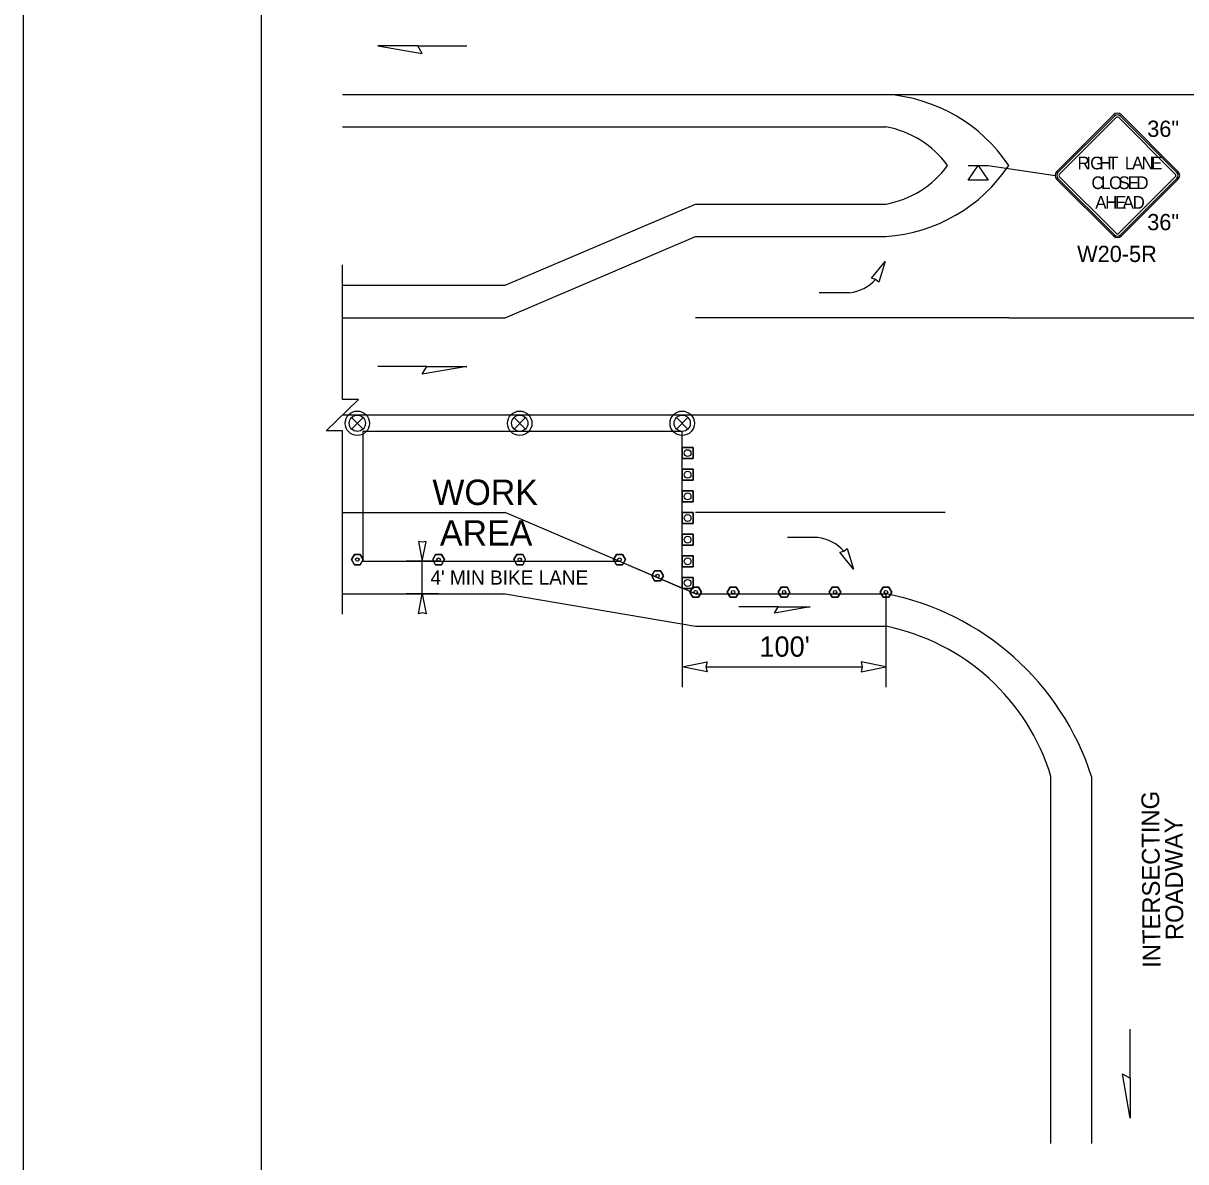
# Model space of a CAD drawing. Extents: x 99958 to 100136, y 99935 to 100013.
# Drawn here: x 100059.062 to 100063.643, y 99971.834 to 99976.321 of the extents above; entities that cross this region are included whole.
import ezdxf

# ---------------------------------------------------------------- set-up
doc = ezdxf.new("R2010")
doc.units = 0
for name, color, linetype in [('RD_ED_ShoulderPavedEdge', 7, 'Continuous'), ('RD_MK_LineEdgeWhite', 7, 'Continuous'), ('RD_MK_LineEdgeYellow', 7, 'Continuous'), ('RD_MK_LineLane', 7, 'Continuous'), ('SH_DE_DetailBody1Text', 7, 'Continuous'), ('SH_GI_PlotLimits', 7, 'Continuous'), ('SH_GI_SheetBorder', 7, 'Continuous'), ('TR_SN_ConstructionSigns', 7, 'Continuous'), ('TR_WZ_ArrowLeftStrRightTurn', 7, 'Continuous'), ('TR_WZ_PortableSignMountBlk-Org', 7, 'Continuous'), ('TR_WZ_TrafficCone', 7, 'Continuous'), ('TR_WZ_TrafficSafetyDrum', 7, 'Continuous'), ('TR_WZ_TubularMarker', 7, 'Continuous'), ('TR_WZ_WorkAreaLabel', 7, 'Continuous'), ('TR_WZ_WorkZoneDetails', 7, 'Continuous'), ('TR_WZ_WorkZoneTextCurrent', 7, 'Continuous')]:
    doc.layers.add(name, color=color, linetype=linetype)

msp = doc.modelspace()

# ---------------------------------------------------------------- linework, layer by layer
at = {"layer": 'RD_ED_ShoulderPavedEdge'}
for p, q in [((100060.32, 99975.9124), (100062.4619, 99975.9124)), ((100060.9619, 99975.2885), (100061.7119, 99975.6084)), ((100061.7119, 99975.6084), (100062.4619, 99975.6084)), ((100060.32, 99975.2885), (100060.9619, 99975.2885)), ((100060.32, 99974.0724), (100060.9619, 99974.0724)), ((100060.9619, 99974.0724), (100061.7119, 99973.9444)), ((100061.7119, 99973.9444), (100062.4619, 99973.9444))]:
    msp.add_line(p, q, dxfattribs=at)
msp.add_lwpolyline([(100063.1119, 99971.9059), (100063.1119, 99973.3524)], dxfattribs=at)
for centre, radius, start, end in [((100062.3952, 99975.5361), 0.3822, 35.9393, 79.9433), ((100062.3952, 99975.9848), 0.3822, 280.0567, 324.0607), ((100062.2915, 99973.1044), 0.8571, 16.8187, 78.5287)]:
    msp.add_arc(centre, radius, start, end, dxfattribs=at)
at = {"layer": 'RD_MK_LineEdgeWhite'}
msp.add_line((100063.2719, 99973.3524), (100063.2719, 99971.9059), dxfattribs=at)
msp.add_arc((100062.257, 99973.0262), 1.0661, 17.8172, 78.9158, dxfattribs=at)
at = {"layer": 'RD_MK_LineEdgeYellow'}
for p, q in [((100060.32, 99976.0404), (100062.4619, 99976.0404)), ((100062.4619, 99976.0404), (100064.3984, 99976.0404)), ((100060.9619, 99975.1604), (100061.7119, 99975.4804)), ((100061.7119, 99975.4804), (100062.4619, 99975.4804)), ((100060.32, 99975.1604), (100060.9619, 99975.1604)), ((100062.9455, 99975.1604), (100064.8819, 99975.1604)), ((100060.32, 99974.3924), (100060.9619, 99974.3924)), ((100061.7119, 99974.0724), (100062.4619, 99974.0724))]:
    msp.add_line(p, q, dxfattribs=at)
for centre, start, end in [((100062.4204, 99975.4112), 33.6284, 86.2234), ((100062.4204, 99976.1097), 273.7766, 326.3716)]:
    msp.add_arc(centre, 0.6306, start, end, dxfattribs=at)
at = {"layer": 'RD_MK_LineLane'}
for points in [[(100062.9455, 99975.1604), (100061.7119, 99975.1604)], [(100067.555, 99974.7764), (100060.32, 99974.7764)], [(100061.7119, 99974.0724), (100060.9619, 99974.3924)], [(100062.6955, 99974.3924), (100061.7119, 99974.3924)]]:
    msp.add_lwpolyline(points, dxfattribs=at)
at = {"layer": 'SH_GI_PlotLimits'}
msp.add_lwpolyline([(100059.0625, 99969.6875), (100076.0625, 99969.6875), (100076.0625, 99980.6875), (100059.0625, 99980.6875)], close=True, dxfattribs=at)
at = {"layer": 'SH_GI_SheetBorder'}
msp.add_line((100060, 99980.375), (100060, 99970), dxfattribs=at)
at = {"layer": 'TR_SN_ConstructionSigns'}
for p, q in [((100063.358, 99975.9599), (100063.1352, 99975.7371)), ((100063.3624, 99975.9554), (100063.1396, 99975.7327)), ((100063.1458, 99975.7265), (100063.3686, 99975.9493)), ((100063.3792, 99975.9493), (100063.6019, 99975.7265)), ((100063.6081, 99975.7327), (100063.3854, 99975.9554)), ((100063.6125, 99975.7371), (100063.3898, 99975.9599)), ((100063.1352, 99975.7053), (100063.358, 99975.4826)), ((100063.1396, 99975.7097), (100063.3624, 99975.487)), ((100063.3686, 99975.4932), (100063.1458, 99975.7159)), ((100063.6019, 99975.7159), (100063.3792, 99975.4932)), ((100063.3854, 99975.487), (100063.6081, 99975.7097)), ((100063.3898, 99975.4826), (100063.6125, 99975.7053))]:
    msp.add_line(p, q, dxfattribs=at)
for centre, radius, start, end in [((100063.3739, 99975.9439), 0.0225, 45, 135), ((100063.3739, 99975.9439), 0.0162, 45, 135), ((100063.3739, 99975.9439), 0.0075, 45, 135), ((100063.1511, 99975.7212), 0.0225, 135, 225), ((100063.1511, 99975.7212), 0.0162, 135, 225), ((100063.1511, 99975.7212), 0.0075, 135, 225), ((100063.5966, 99975.7212), 0.0075, 315, 45), ((100063.5966, 99975.7212), 0.0162, 315, 45), ((100063.5966, 99975.7212), 0.0225, 315, 45), ((100063.3739, 99975.4985), 0.0162, 225, 315), ((100063.3739, 99975.4985), 0.0075, 225, 315), ((100063.3739, 99975.4985), 0.0225, 225, 315)]:
    msp.add_arc(centre, radius, start, end, dxfattribs=at)
at = {"layer": 'TR_WZ_ArrowLeftStrRightTurn'}
for p, q in [((100062.3186, 99975.2587), (100062.1986, 99975.2587)), ((100062.1938, 99974.2942), (100062.0738, 99974.2942))]:
    msp.add_line(p, q, dxfattribs=at)
for points in [[(100062.4588, 99975.3822), (100062.4338, 99975.3003), (100062.4211, 99975.3115), (100062.4047, 99975.3158)], [(100062.3336, 99974.1692), (100062.2798, 99974.2359), (100062.2962, 99974.2402), (100062.309, 99974.2513)]]:
    msp.add_lwpolyline(points, close=True, dxfattribs=at)
for centre, radius, start, end in [((100062.2994, 99975.4218), 0.1642, 276.7058, 317.7833), ((100062.1725, 99974.1297), 0.1658, 41.7524, 82.6149)]:
    msp.add_arc(centre, radius, start, end, dxfattribs=at)
at = {"layer": 'TR_WZ_PortableSignMountBlk-Org'}
msp.add_line((100062.7851, 99975.7604), (100062.8651, 99975.7604), dxfattribs=at)
msp.add_lwpolyline([(100062.825, 99975.7604), (100062.8651, 99975.703), (100062.7851, 99975.703)], close=True, dxfattribs=at)
at = {"layer": 'TR_WZ_TrafficCone'}
for points in [[(100061.7016, 99974.6485), (100061.7016, 99974.6058), (100061.6589, 99974.6058), (100061.6589, 99974.6485), (100061.7016, 99974.6485)], [(100061.6589, 99974.6485), (100061.6589, 99974.6058), (100061.7016, 99974.6058), (100061.7016, 99974.6485), (100061.6589, 99974.6485)], [(100061.7016, 99974.5631), (100061.7016, 99974.5205), (100061.6589, 99974.5205), (100061.6589, 99974.5631), (100061.7016, 99974.5631)], [(100061.6589, 99974.5631), (100061.6589, 99974.5205), (100061.7016, 99974.5205), (100061.7016, 99974.5631), (100061.6589, 99974.5631)], [(100061.7016, 99974.4778), (100061.7016, 99974.4351), (100061.6589, 99974.4351), (100061.6589, 99974.4778), (100061.7016, 99974.4778)], [(100061.6589, 99974.4778), (100061.6589, 99974.4351), (100061.7016, 99974.4351), (100061.7016, 99974.4778), (100061.6589, 99974.4778)], [(100061.7016, 99974.3924), (100061.7016, 99974.3498), (100061.6589, 99974.3498), (100061.6589, 99974.3924), (100061.7016, 99974.3924)], [(100061.6589, 99974.3924), (100061.6589, 99974.3498), (100061.7016, 99974.3498), (100061.7016, 99974.3924), (100061.6589, 99974.3924)], [(100061.7016, 99974.3071), (100061.7016, 99974.2644), (100061.6589, 99974.2644), (100061.6589, 99974.3071), (100061.7016, 99974.3071)], [(100061.6589, 99974.3071), (100061.6589, 99974.2644), (100061.7016, 99974.2644), (100061.7016, 99974.3071), (100061.6589, 99974.3071)], [(100061.7016, 99974.2218), (100061.7016, 99974.1791), (100061.6589, 99974.1791), (100061.6589, 99974.2218), (100061.7016, 99974.2218)], [(100061.6589, 99974.2218), (100061.6589, 99974.1791), (100061.7016, 99974.1791), (100061.7016, 99974.2218), (100061.6589, 99974.2218)], [(100061.7016, 99974.1364), (100061.7016, 99974.0938), (100061.6589, 99974.0938), (100061.6589, 99974.1364), (100061.7016, 99974.1364)], [(100061.6589, 99974.1364), (100061.6589, 99974.0938), (100061.7016, 99974.0938), (100061.7016, 99974.1364), (100061.6589, 99974.1364)]]:
    msp.add_lwpolyline(points, dxfattribs=at)
for centre in [(100061.6803, 99974.6271), (100061.6803, 99974.5418), (100061.6803, 99974.4564), (100061.6803, 99974.3711), (100061.6803, 99974.2858), (100061.6803, 99974.2004), (100061.6803, 99974.1151)]:
    msp.add_circle(centre, 0.0133, dxfattribs=at)
at = {"layer": 'TR_WZ_TrafficSafetyDrum'}
for p, q in [((100060.3563, 99974.7671), (100060.4015, 99974.7218)), ((100060.4015, 99974.7671), (100060.3563, 99974.7218)), ((100060.9963, 99974.7671), (100061.0415, 99974.7218)), ((100061.0415, 99974.7671), (100060.9963, 99974.7218)), ((100061.6363, 99974.7671), (100061.6815, 99974.7218)), ((100061.6815, 99974.7671), (100061.6363, 99974.7218))]:
    msp.add_line(p, q, dxfattribs=at)
for centre, radius in [((100060.3789, 99974.7445), 0.048), ((100060.3789, 99974.7445), 0.048), ((100060.3789, 99974.7445), 0.032), ((100061.0189, 99974.7445), 0.048), ((100061.0189, 99974.7445), 0.048), ((100061.0189, 99974.7445), 0.032), ((100061.6589, 99974.7445), 0.048), ((100061.6589, 99974.7445), 0.048), ((100061.6589, 99974.7445), 0.032)]:
    msp.add_circle(centre, radius, dxfattribs=at)
at = {"layer": 'TR_WZ_TubularMarker'}
for points in [[(100060.3558, 99974.2071), (100060.3674, 99974.2271), (100060.3905, 99974.2271), (100060.402, 99974.2071), (100060.3905, 99974.1871), (100060.3674, 99974.1871)], [(100060.6758, 99974.2071), (100060.6874, 99974.2271), (100060.7105, 99974.2271), (100060.722, 99974.2071), (100060.7105, 99974.1871), (100060.6874, 99974.1871)], [(100060.9958, 99974.2071), (100061.0074, 99974.2271), (100061.0305, 99974.2271), (100061.042, 99974.2071), (100061.0305, 99974.1871), (100061.0074, 99974.1871)], [(100061.3888, 99974.2071), (100061.4004, 99974.2271), (100061.4235, 99974.2271), (100061.435, 99974.2071), (100061.4235, 99974.1871), (100061.4004, 99974.1871)], [(100061.5388, 99974.1431), (100061.5504, 99974.1631), (100061.5735, 99974.1631), (100061.585, 99974.1431), (100061.5735, 99974.1231), (100061.5504, 99974.1231)], [(100061.6888, 99974.0791), (100061.7004, 99974.0991), (100061.7235, 99974.0991), (100061.735, 99974.0791), (100061.7235, 99974.0591), (100061.7004, 99974.0591)], [(100061.8366, 99974.0791), (100061.8481, 99974.0991), (100061.8712, 99974.0991), (100061.8828, 99974.0791), (100061.8712, 99974.0591), (100061.8481, 99974.0591)], [(100062.0373, 99974.0791), (100062.0489, 99974.0991), (100062.072, 99974.0991), (100062.0835, 99974.0791), (100062.072, 99974.0591), (100062.0489, 99974.0591)], [(100062.2381, 99974.0791), (100062.2496, 99974.0991), (100062.2727, 99974.0991), (100062.2843, 99974.0791), (100062.2727, 99974.0591), (100062.2496, 99974.0591)], [(100062.4388, 99974.0791), (100062.4504, 99974.0991), (100062.4735, 99974.0991), (100062.485, 99974.0791), (100062.4735, 99974.0591), (100062.4504, 99974.0591)]]:
    msp.add_lwpolyline(points, close=True, dxfattribs=at)
for points in [[(100060.3674, 99974.1871), (100060.3905, 99974.1871), (100060.402, 99974.2071), (100060.3905, 99974.2271), (100060.3674, 99974.2271), (100060.3558, 99974.2071), (100060.3674, 99974.1871)], [(100060.6874, 99974.1871), (100060.7105, 99974.1871), (100060.722, 99974.2071), (100060.7105, 99974.2271), (100060.6874, 99974.2271), (100060.6758, 99974.2071), (100060.6874, 99974.1871)], [(100061.0074, 99974.1871), (100061.0305, 99974.1871), (100061.042, 99974.2071), (100061.0305, 99974.2271), (100061.0074, 99974.2271), (100060.9958, 99974.2071), (100061.0074, 99974.1871)], [(100061.4004, 99974.1871), (100061.4235, 99974.1871), (100061.435, 99974.2071), (100061.4235, 99974.2271), (100061.4004, 99974.2271), (100061.3888, 99974.2071), (100061.4004, 99974.1871)], [(100061.5504, 99974.1231), (100061.5735, 99974.1231), (100061.585, 99974.1431), (100061.5735, 99974.1631), (100061.5504, 99974.1631), (100061.5388, 99974.1431), (100061.5504, 99974.1231)], [(100061.7004, 99974.0591), (100061.7235, 99974.0591), (100061.735, 99974.0791), (100061.7235, 99974.0991), (100061.7004, 99974.0991), (100061.6888, 99974.0791), (100061.7004, 99974.0591)], [(100061.8481, 99974.0591), (100061.8712, 99974.0591), (100061.8828, 99974.0791), (100061.8712, 99974.0991), (100061.8481, 99974.0991), (100061.8366, 99974.0791), (100061.8481, 99974.0591)], [(100062.0489, 99974.0591), (100062.072, 99974.0591), (100062.0835, 99974.0791), (100062.072, 99974.0991), (100062.0489, 99974.0991), (100062.0373, 99974.0791), (100062.0489, 99974.0591)], [(100062.2496, 99974.0591), (100062.2727, 99974.0591), (100062.2843, 99974.0791), (100062.2727, 99974.0991), (100062.2496, 99974.0991), (100062.2381, 99974.0791), (100062.2496, 99974.0591)], [(100062.4504, 99974.0591), (100062.4735, 99974.0591), (100062.485, 99974.0791), (100062.4735, 99974.0991), (100062.4504, 99974.0991), (100062.4388, 99974.0791), (100062.4504, 99974.0591)]]:
    msp.add_lwpolyline(points, dxfattribs=at)
for centre in [(100060.3789, 99974.2071), (100060.6989, 99974.2071), (100061.0189, 99974.2071), (100061.4119, 99974.2071), (100061.5619, 99974.1431), (100061.7119, 99974.0791), (100061.8597, 99974.0791), (100062.0604, 99974.0791), (100062.2612, 99974.0791), (100062.4619, 99974.0791)]:
    msp.add_circle(centre, 0.00667, dxfattribs=at)
at = {"layer": 'TR_WZ_WorkZoneDetails'}
for p, q in [((100060.6169, 99976.2324), (100060.8098, 99976.2324)), ((100062.8651, 99975.7604), (100063.1286, 99975.7212)), ((100060.6526, 99974.9685), (100060.4597, 99974.9685)), ((100060.6989, 99974.2004), (100060.5709, 99974.2004)), ((100060.6349, 99974.0724), (100060.6349, 99974.2004)), ((100060.6989, 99974.0724), (100060.5709, 99974.0724)), ((100061.6589, 99974.0951), (100061.6589, 99973.7045)), ((100062.4619, 99974.0724), (100062.4619, 99973.7045)), ((100062.0368, 99974.0208), (100061.8825, 99974.0208)), ((100061.7526, 99973.7845), (100062.3682, 99973.7845)), ((100063.4242, 99972.1631), (100063.4242, 99972.356))]:
    msp.add_line(p, q, dxfattribs=at)
for points in [[(100060.4597, 99976.2324), (100060.6347, 99976.2016), (100060.6169, 99976.2324)], [(100060.8098, 99974.9685), (100060.6347, 99974.9376), (100060.6526, 99974.9685)], [(100060.4, 99974.2004), (100060.9619, 99974.2004), (100061.4119, 99974.2004), (100061.6589, 99974.0951), (100061.6589, 99974.0951), (100061.6589, 99974.4038), (100061.6589, 99974.7124), (100061.0295, 99974.7125), (100060.4, 99974.7124)], [(100060.6349, 99974.2004), (100060.6503, 99974.2791), (100060.6349, 99974.2754), (100060.6195, 99974.2791)], [(100060.6349, 99974.0724), (100060.6503, 99973.9938), (100060.6349, 99973.9975), (100060.6195, 99973.9938)], [(100062.1626, 99974.0208), (100062.0226, 99973.9961), (100062.0368, 99974.0208)], [(100061.6589, 99973.7845), (100061.7572, 99973.8037), (100061.7526, 99973.7845), (100061.7572, 99973.7652)], [(100062.4619, 99973.7845), (100062.3637, 99973.8037), (100062.3682, 99973.7845), (100062.3637, 99973.7652)], [(100063.4242, 99972.0059), (100063.3933, 99972.181), (100063.4242, 99972.1631)]]:
    msp.add_lwpolyline(points, close=True, dxfattribs=at)
msp.add_lwpolyline([(100060.32, 99973.9924), (100060.32, 99974.7145), (100060.256, 99974.7145), (100060.384, 99974.8384), (100060.32, 99974.8384), (100060.32, 99975.3685)], dxfattribs=at)

# ---------------------------------------------------------------- texts
at = {"layer": 'SH_DE_DetailBody1Text'}
for s, p in [('INTERSECTING', (100063.5437, 99972.5989)), ('ROADWAY', (100063.6339, 99972.7079))]:
    msp.add_text(s, height=0.07, rotation=90.4626, dxfattribs=at).set_placement(p)
at = {"layer": 'TR_SN_ConstructionSigns'}
for s, p in [('36"', (100063.4913, 99975.8731)), ('36"', (100063.4913, 99975.5054)), ('W20-5R', (100063.2151, 99975.38))]:
    msp.add_text(s, height=0.064, rotation=360, dxfattribs=at).set_placement(p)
for s, p in [('R', (100063.2164, 99975.745)), ('I', (100063.2513, 99975.745)), ('G', (100063.2666, 99975.745)), ('H', (100063.3028, 99975.745)), ('T', (100063.3365, 99975.745)), ('L', (100063.4031, 99975.745)), ('A', (100063.4311, 99975.745)), ('N', (100063.4688, 99975.745)), ('E', (100063.5059, 99975.745)), ('C', (100063.2714, 99975.6675)), ('L', (100063.3094, 99975.6675)), ('O', (100063.3409, 99975.6675)), ('S', (100063.3779, 99975.6675)), ('E', (100063.4144, 99975.6675)), ('D', (100063.4484, 99975.6675)), ('A', (100063.2864, 99975.59)), ('H', (100063.3254, 99975.59)), ('E', (100063.3644, 99975.59)), ('A', (100063.3944, 99975.59)), ('D', (100063.4334, 99975.59))]:
    msp.add_text(s, height=0.05, dxfattribs=at).set_placement(p)
at = {"layer": 'TR_WZ_WorkAreaLabel'}
for s, p in [('WORK', (100060.6746, 99974.4225)), ('AREA', (100060.7043, 99974.2624))]:
    msp.add_text(s, height=0.1, dxfattribs=at).set_placement(p)
at = {"layer": 'TR_WZ_WorkZoneTextCurrent'}
for s, height, p in [("4' MIN BIKE LANE", 0.056, (100060.6669, 99974.1084)), ("100'", 0.08, (100061.963, 99973.8245))]:
    msp.add_text(s, height=height, dxfattribs=at).set_placement(p)

doc.saveas('drawing.dxf')
